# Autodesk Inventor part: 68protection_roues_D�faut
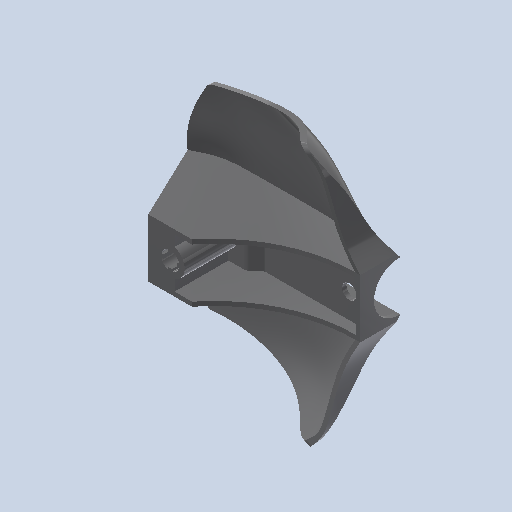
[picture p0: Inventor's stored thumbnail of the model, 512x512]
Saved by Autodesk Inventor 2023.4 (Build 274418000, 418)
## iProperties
Created: 2011-01
Part Number: 68protection_roues_D�faut
Document SubType Name: Modeling
Designer: eric
Density: 1 g/cm^3
Mass: 108.102 g
Surface Area: 731.26 cm^2
Volume: 108.102 cm^3
Material: Générique
Appearance: Lisse - Gris moyen
Author: eric
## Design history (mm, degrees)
feature "Base1"
node "Corps solides"
node "Corps surfaciques"
node "Solide1"
